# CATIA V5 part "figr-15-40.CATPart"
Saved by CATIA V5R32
Part number: Part1
Bounding box of the stored display mesh (mm): x -55.204 to 69.266, y -33.79 to 44.107, z 0 to 118.408
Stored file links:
  D:\PROJECTS\Project 2022\CATIA V5 6R 2022\Resources\Part Files\c15_catia_v5_6r2022_prt\figr-15-40.CATPart
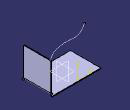
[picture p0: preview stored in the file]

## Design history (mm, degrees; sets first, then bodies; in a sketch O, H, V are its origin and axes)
SheetMetalParameters1: Thickness 2, BendRadius 4, KFactor 0.400515 {= log(min(100,max(20*SheetMetalParameters1.BendRadius,SheetMetalParameters1.Thickness)/SheetMetalParameters1.Thickness))/log(100)/2}, ReliefRadialLength 1, ReliefAxialLength 2, MinimumBendRadius 0
Body1 (main body)
  Sketch1 on xy-plane, origin (0, 0, 0), H (1, 0, 0), V (0, 1, 0)
    line L1 (-55.2037, 44.1067) -> (69.266, 44.1067)
    line L2 (69.266, 44.1067) -> (69.266, -33.7896)
    line L3 (69.266, -33.7896) -> (-55.2037, -33.7896)
    line L4 (-55.2037, -33.7896) -> (-55.2037, 44.1067)
    horizontal: L1 H, L3 H
    vertical: L2 V, L4 V
  Wall1: Thickness 2, Profile Sketch1, OffsetValue 0
  d_NewWallOnEdge1: NewWallOnEdge_Length 77.8964, NewWallOnEdge_HeightLimitOffset 0, NewWallOnEdge_WidthOffset1 -4, NewWallOnEdge_WidthOffset2 -4, NewWallOnEdge_Angle 90, NewWallOnEdge_BendRadiusValue 4 {= SheetMetalParameters1.BendRadius}, NewWallOnEdge_BendTable SheetMetalParameters1, NewWallOnEdge_Edge edge [face of Wall1 | face of Wall1], NewWallOnEdge_GapValue 0, KFacteur 0.400515 {= log(min(100,max(20*d_NewWallOnEdge1.Radius,SheetMetalParameters1.Thickness)/SheetMetalParameters1.Thickness))/log(100)/2}
  Sketch2 on face of d_NewWallOnEdge1, origin (0, 40.1067, 0), H (-1, 0, 0), V (0, 0, 1)
    spline S1 through (-69.266, 77.8964) (-67.9767, 84.9607) (-48.7678, 98.5965) (6.1586, 103.3856) (17.3621, 118.4076)
    reference projected line E1 (-69.266, 6) -> (-69.266, 77.8964) from edge [face of d_NewWallOnEdge1 | face of d_NewWallOnEdge1]
    reference projected line E2 (-69.266, 6) -> (-69.266, 77.8964) from edge [face of d_NewWallOnEdge1 | face of d_NewWallOnEdge1]
    reference projected point E3 (-69.266, 77.8964) from vertex [face of d_NewWallOnEdge1 | face of d_NewWallOnEdge1 | face of d_NewWallOnEdge1]
    point P1 (-69.266, 77.8964)
    coincidence: P1 E1, P1 E3
    tangency: S1 E2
